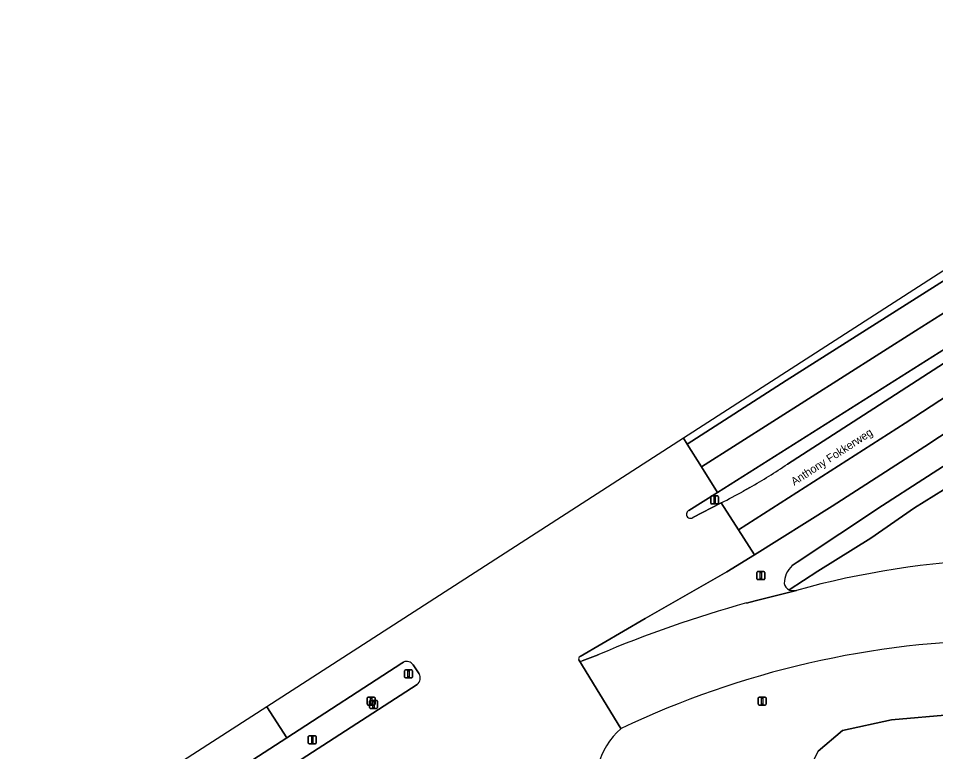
# Model space of a CAD drawing. Extents: x 156061 to 157804, y 383437 to 385640.
# Drawn here: x 156312.5 to 156427.2, y 385531.8 to 385623.4 of the extents above; entities that cross this region are included whole.
import ezdxf

# ---------------------------------------------------------------- set-up
doc = ezdxf.new("R2010")
doc.units = 0
for name, color, linetype in [('IMGEO_Afsluitpaal', 7, 'Continuous'), ('IMGEO_Berm_groen', 7, 'Continuous'), ('IMGEO_Groenvoorziening', 7, 'Continuous'), ('IMGEO_Lichtmast', 7, 'Continuous'), ('IMGEO_Openbare_ruimte_label', 7, 'Continuous'), ('IMGEO_Rijbaan_regionaal_gesloten', 7, 'Continuous'), ('IMGEO_Verkeersregelinstallatiepaal', 7, 'Continuous')]:
    doc.layers.add(name, color=color, linetype=linetype)

msp = doc.modelspace()

# ---------------------------------------------------------------- linework, layer by layer
at = {"layer": 'IMGEO_Afsluitpaal'}
for p, q in [((156360.89, 385542.03), (156361.68, 385542.03)), ((156361.68, 385542.03), (156360.89, 385542.03)), ((156360.79, 385541.13), (156360.79, 385541.93)), ((156360.79, 385541.93), (156360.79, 385541.13)), ((156361.68, 385541.03), (156360.89, 385541.03)), ((156360.89, 385541.03), (156361.68, 385541.03)), ((156361.78, 385541.93), (156361.78, 385541.13)), ((156361.78, 385541.13), (156361.78, 385541.93))]:
    msp.add_line(p, q, dxfattribs=at)
msp.add_lwpolyline([(156361.21, 385541.91), (156361.36, 385541.91), (156361.36, 385541.16), (156361.21, 385541.16), (156361.21, 385541.91)], dxfattribs=at)
for centre, start, end in [((156360.89, 385541.93), 90, 180), ((156360.89, 385541.93), 90, 180), ((156361.68, 385541.93), 0, 90), ((156361.68, 385541.93), 360, 90), ((156360.89, 385541.13), 180, 270), ((156360.89, 385541.13), 180, 270), ((156361.68, 385541.13), 270, 0), ((156361.68, 385541.13), 270, 0)]:
    msp.add_arc(centre, 0.1, start, end, dxfattribs=at)
at = {"layer": 'IMGEO_Berm_groen'}
for points in [[(156457.74, 385603.2), (156468.38, 385609.76), (156480.27, 385617.44), (156479.29, 385619.28), (156457.09, 385604.88), (156455.56, 385603.39), (156444.2, 385592.17), (156399.89, 385564.2), (156396.33, 385561.96)], [(156444.61, 385578.21), (156455.02, 385584.79), (156465.42, 385591.01), (156476.98, 385597.97), (156487.09, 385604.63), (156485.35, 385607.89), (156485.17, 385608.23), (156485.15, 385608.27), (156484.49, 385607.86), (156457.48, 385590.81), (156425.8, 385569.95), (156414.23, 385562.48), (156404.5, 385556.42), (156401.07, 385554.28), (156390.85, 385548.47), (156382.74, 385543.7)], [(156408.65, 385567.73), (156419.41, 385574.67), (156445.92, 385591.78), (156451.49, 385597.23), (156457.74, 385603.2)], [(156448.31, 385577.75), (156469.59, 385590.66), (156475.53, 385594.14), (156477.95, 385595.67), (156479.09, 385596.28), (156479.97, 385596.92), (156480.06, 385597.32), (156479.81, 385597.66), (156479.16, 385598.78), (156477.29, 385597.6), (156477.23, 385597.74), (156477.09, 385597.89), (156476.98, 385597.97), (156465.42, 385591.01), (156455.02, 385584.79), (156444.61, 385578.21), (156435.65, 385572.32), (156420.52, 385562.55), (156409.83, 385555.49), (156409.23, 385555.06)], [(156408.84, 385552.01), (156412.43, 385554.36), (156419.05, 385558.49), (156424.52, 385562.26), (156435.37, 385569.02), (156448.31, 385577.75)], [(156409.23, 385555.06), (156409.83, 385555.49), (156420.52, 385562.55), (156435.65, 385572.32), (156444.61, 385578.21)], [(156403.12, 385564.35), (156403.94, 385564.81)], [(156396.81, 385561.05), (156400.34, 385562.89)], [(156403.53, 385550.38), (156404.62, 385550.66), (156408.45, 385551.63), (156409.77, 385551.96)], [(156382.96, 385543.18), (156384.96, 385543.9)], [(156360.66, 385543), (156360.46, 385542.87), (156346.09, 385533.56), (156314.1, 385512.84), (156302.47, 385505.41), (156290.49, 385497.87), (156278.52, 385490.5), (156266.95, 385483.55), (156254.78, 385476.36), (156243.16, 385469.51), (156215.23, 385452.76), (156213.93, 385451.91), (156195.47, 385439.96), (156146.25, 385408.11), (156122.36, 385392.42), (156089.02, 385370.47), (156093.27, 385365.39), (156145.76, 385399.91), (156224.68, 385450.98), (156281.69, 385487.99)], [(156362.63, 385541.55), (156361.86, 385542.66)], [(156281.69, 385487.99), (156347.87, 385530.83), (156362.36, 385540.21)]]:
    msp.add_lwpolyline(points, dxfattribs=at)
for centre, radius, start, end in [((156366.85, 385629.96), 74.96, 299.6531, 303.8885), ((156367.11, 385629.37), 74.32, 296.5575, 298.9833), ((156396.53, 385561.48), 0.514, 112.6751, 303.3116), ((156411.21, 385552.84), 2.97, 131.8011, 180.4497), ((156411.21, 385552.84), 2.97, 131.8011, 180.4497), ((156409.35, 385553.02), 1.13, 190.1722, 243.0679), ((156409.35, 385553.02), 1.13, 190.1722, 243.0679), ((156409.41, 385554.2), 2.27, 255.3537, 279.1177), ((156442.04, 385410.19), 145.39, 105.3614, 113.1203), ((156382.81, 385543.42), 0.286, 104.0075, 212.3897), ((156382.81, 385543.42), 0.286, 212.5197, 303.0942), ((156361.07, 385542.15), 0.941, 32.4846, 115.7756), ((156361.67, 385541.05), 1.08, 309.1218, 27.5505)]:
    msp.add_arc(centre, radius, start, end, dxfattribs=at)
at = {"layer": 'IMGEO_Groenvoorziening'}
for points in [[(156468.78, 385577.15), (156480.52, 385584.84), (156488.02, 385589.35), (156488.76, 385590.11), (156490.06, 385591.44), (156490.74, 385593.18), (156490.76, 385594.73), (156490.37, 385597.17), (156489.79, 385599.31), (156488.68, 385601.91), (156488.03, 385602.99), (156479.81, 385597.66), (156480.06, 385597.32), (156479.97, 385596.92), (156479.09, 385596.28), (156477.95, 385595.67), (156475.53, 385594.14), (156469.59, 385590.66), (156448.31, 385577.75), (156435.37, 385569.02), (156424.52, 385562.26), (156419.05, 385558.49), (156412.43, 385554.36), (156408.84, 385552.01)], [(156421.05, 385521.05), (156420.41, 385521.52), (156415.25, 385524.03), (156410.61, 385528.11), (156412.46, 385531.88), (156415.53, 385534.45), (156421.65, 385535.79), (156429.28, 385536.44), (156437.02, 385537.14), (156443.94, 385536.91), (156448.64, 385536.45)], [(156448.64, 385536.45), (156443.94, 385536.91), (156437.02, 385537.14), (156429.28, 385536.44), (156421.65, 385535.79), (156415.53, 385534.45), (156412.46, 385531.88), (156410.61, 385528.11), (156415.25, 385524.03), (156420.41, 385521.52), (156421.05, 385521.05)]]:
    msp.add_lwpolyline(points, dxfattribs=at)
for centre, radius, start, end in [((156439.11, 385445.67), 110.27, 92.3086, 105.432), ((156409.41, 385554.2), 2.27, 255.3537, 279.1177), ((156436.88, 385431.39), 114.37, 90.4701, 115.3908), ((156393.85, 385527.79), 9.17, 130.9564, 200.9024)]:
    msp.add_arc(centre, radius, start, end, dxfattribs=at)
at = {"layer": 'IMGEO_Lichtmast'}
for p, q in [((156404.81, 385553.41), (156404.81, 385554.21)), ((156404.81, 385554.21), (156404.81, 385553.41)), ((156404.91, 385554.31), (156405.7, 385554.31)), ((156405.7, 385554.31), (156404.91, 385554.31)), ((156405.8, 385554.21), (156405.8, 385553.41)), ((156405.8, 385553.41), (156405.8, 385554.21)), ((156405.7, 385553.31), (156404.91, 385553.31)), ((156404.91, 385553.31), (156405.7, 385553.31)), ((156405.08, 385538.63), (156405.87, 385538.63)), ((156405.87, 385538.63), (156405.08, 385538.63)), ((156404.98, 385537.73), (156404.98, 385538.53)), ((156404.98, 385538.53), (156404.98, 385537.73)), ((156405.87, 385537.63), (156405.08, 385537.63)), ((156405.08, 385537.63), (156405.87, 385537.63)), ((156405.97, 385538.53), (156405.97, 385537.73)), ((156405.97, 385537.73), (156405.97, 385538.53))]:
    msp.add_line(p, q, dxfattribs=at)
for points in [[(156405.23, 385554.18), (156405.38, 385554.18), (156405.38, 385553.43), (156405.23, 385553.43), (156405.23, 385554.18)], [(156405.4, 385538.51), (156405.55, 385538.51), (156405.55, 385537.76), (156405.4, 385537.76), (156405.4, 385538.51)]]:
    msp.add_lwpolyline(points, dxfattribs=at)
for centre, start, end in [((156404.91, 385554.21), 90, 180), ((156404.91, 385554.21), 90, 180), ((156405.7, 385554.21), 0, 90), ((156405.7, 385554.21), 360, 90), ((156404.91, 385553.41), 180, 270), ((156404.91, 385553.41), 180, 270), ((156405.7, 385553.41), 270, 0), ((156405.7, 385553.41), 270, 0), ((156405.08, 385538.53), 90, 180), ((156405.08, 385538.53), 90, 180), ((156405.87, 385538.53), 0, 90), ((156405.87, 385538.53), 360, 90), ((156405.08, 385537.73), 180, 270), ((156405.08, 385537.73), 180, 270), ((156405.87, 385537.73), 270, 0), ((156405.87, 385537.73), 270, 0)]:
    msp.add_arc(centre, 0.1, start, end, dxfattribs=at)
at = {"layer": 'IMGEO_Rijbaan_regionaal_gesloten'}
for points in [[(156395.65, 385570.97), (156396.11, 385570.23), (156408.46, 385578.16), (156443.47, 385600.32), (156460.47, 385611.21), (156477.84, 385622.02), (156477.19, 385623.23), (156477.09, 385623.42)], [(156457.09, 385604.88), (156479.29, 385619.28), (156478.07, 385621.57), (156477.84, 385622.02), (156460.47, 385611.21), (156443.47, 385600.32), (156408.46, 385578.16), (156396.11, 385570.23), (156397.88, 385567.41), (156424.62, 385584.37)], [(156457.48, 385590.81), (156484.49, 385607.86), (156485.15, 385608.27), (156483.26, 385611.82), (156471.7, 385604.33), (156458, 385595.49), (156423.35, 385572.86), (156402.5, 385559.52), (156404.5, 385556.42), (156414.23, 385562.48), (156425.8, 385569.95)], [(156444.2, 385592.17), (156455.56, 385603.39), (156457.09, 385604.88), (156424.62, 385584.37), (156397.88, 385567.41), (156399.89, 385564.2)]]:
    msp.add_lwpolyline(points, close=True, dxfattribs=at)
for points in [[(156458, 385595.49), (156471.7, 385604.33), (156483.26, 385611.82), (156481.73, 385614.7), (156445.92, 385591.78), (156419.41, 385574.67), (156408.65, 385567.73)], [(156400.34, 385562.89), (156402.5, 385559.52), (156423.35, 385572.86), (156458, 385595.49)], [(156396.33, 385561.96), (156399.89, 385564.2), (156397.88, 385567.41), (156396.11, 385570.23), (156395.65, 385570.97), (156343.56, 385537.43)], [(156403.94, 385564.81), (156403.12, 385564.35)], [(156382.74, 385543.7), (156390.85, 385548.47), (156401.07, 385554.28), (156404.5, 385556.42), (156402.5, 385559.52), (156400.34, 385562.89), (156396.81, 385561.05)], [(156409.77, 385551.96), (156408.45, 385551.63), (156404.62, 385550.66), (156403.53, 385550.38)], [(156382.57, 385543.27), (156387.83, 385534.72)], [(156387.83, 385534.72), (156382.57, 385543.27)], [(156384.96, 385543.9), (156382.96, 385543.18)], [(156343.56, 385537.43), (156346.09, 385533.56), (156360.46, 385542.87), (156360.66, 385543)], [(156361.86, 385542.66), (156362.63, 385541.55)], [(156362.36, 385540.21), (156347.87, 385530.83), (156357.59, 385515.73), (156362.88, 385518.97)], [(156083.92, 385370.25), (156085.61, 385368.22), (156089.02, 385370.47), (156122.36, 385392.42), (156146.25, 385408.11), (156195.47, 385439.96), (156213.93, 385451.91), (156215.23, 385452.76), (156243.16, 385469.51), (156254.78, 385476.36), (156266.95, 385483.55), (156278.52, 385490.5), (156290.49, 385497.87), (156302.47, 385505.41), (156314.1, 385512.84), (156346.09, 385533.56), (156343.56, 385537.43), (156083.92, 385370.25)]]:
    msp.add_lwpolyline(points, dxfattribs=at)
for centre, radius, start, end in [((156366.85, 385629.96), 74.96, 299.6531, 303.8885), ((156367.11, 385629.37), 74.32, 296.5575, 298.9833), ((156396.53, 385561.48), 0.514, 112.6751, 303.3116), ((156439.11, 385445.67), 110.27, 92.3086, 105.432), ((156442.04, 385410.19), 145.39, 105.3614, 113.1203), ((156436.88, 385431.39), 114.37, 90.4701, 115.3908), ((156382.81, 385543.42), 0.286, 104.0075, 212.3897), ((156382.81, 385543.42), 0.286, 212.5197, 303.0942), ((156361.07, 385542.15), 0.941, 32.4846, 115.7756), ((156361.67, 385541.05), 1.08, 309.1218, 27.5505), ((156393.85, 385527.79), 9.17, 130.9564, 200.9024)]:
    msp.add_arc(centre, radius, start, end, dxfattribs=at)
at = {"layer": 'IMGEO_Verkeersregelinstallatiepaal'}
for p, q in [((156399.04, 385562.86), (156399.04, 385563.66)), ((156399.04, 385563.66), (156399.04, 385562.86)), ((156399.14, 385563.76), (156399.92, 385563.76)), ((156399.92, 385563.76), (156399.14, 385563.76)), ((156399.92, 385562.76), (156399.14, 385562.76)), ((156399.14, 385562.76), (156399.92, 385562.76)), ((156400.02, 385563.66), (156400.02, 385562.86)), ((156400.02, 385562.86), (156400.02, 385563.66)), ((156356.21, 385538.63), (156357, 385538.63)), ((156357, 385538.63), (156356.21, 385538.63)), ((156356.11, 385537.73), (156356.11, 385538.53)), ((156356.11, 385538.53), (156356.11, 385537.73)), ((156357, 385537.63), (156356.21, 385537.63)), ((156356.21, 385537.63), (156357, 385537.63)), ((156356.4, 385537.32), (156356.4, 385538.12)), ((156356.4, 385538.12), (156356.4, 385537.32)), ((156356.5, 385538.22), (156357.29, 385538.22)), ((156357.29, 385538.22), (156356.5, 385538.22)), ((156357.1, 385538.53), (156357.1, 385537.73)), ((156357.1, 385537.73), (156357.1, 385538.53)), ((156357.39, 385538.12), (156357.39, 385537.32)), ((156357.39, 385537.32), (156357.39, 385538.12)), ((156357.29, 385537.22), (156356.5, 385537.22)), ((156356.5, 385537.22), (156357.29, 385537.22)), ((156348.76, 385532.89), (156348.76, 385533.69)), ((156348.76, 385533.69), (156348.76, 385532.89)), ((156348.86, 385533.79), (156349.65, 385533.79)), ((156349.65, 385533.79), (156348.86, 385533.79)), ((156349.75, 385533.69), (156349.75, 385532.89)), ((156349.75, 385532.89), (156349.75, 385533.69)), ((156349.65, 385532.79), (156348.86, 385532.79)), ((156348.86, 385532.79), (156349.65, 385532.79))]:
    msp.add_line(p, q, dxfattribs=at)
for points in [[(156399.46, 385563.63), (156399.61, 385563.63), (156399.61, 385562.88), (156399.46, 385562.88), (156399.46, 385563.63)], [(156356.53, 385538.51), (156356.68, 385538.51), (156356.68, 385537.76), (156356.53, 385537.76), (156356.53, 385538.51)], [(156356.82, 385538.09), (156356.97, 385538.09), (156356.97, 385537.34), (156356.82, 385537.34), (156356.82, 385538.09)], [(156349.18, 385533.67), (156349.33, 385533.67), (156349.33, 385532.92), (156349.18, 385532.92), (156349.18, 385533.67)]]:
    msp.add_lwpolyline(points, dxfattribs=at)
for centre, start, end in [((156399.14, 385563.66), 90, 180), ((156399.14, 385563.66), 90, 180), ((156399.14, 385562.86), 180, 270), ((156399.14, 385562.86), 180, 270), ((156399.92, 385563.66), 0, 90), ((156399.92, 385563.66), 360, 90), ((156399.92, 385562.86), 270, 0), ((156399.92, 385562.86), 270, 0), ((156356.21, 385538.53), 90, 180), ((156356.21, 385538.53), 90, 180), ((156357, 385538.53), 0, 90), ((156357, 385538.53), 360, 90), ((156356.21, 385537.73), 180, 270), ((156356.21, 385537.73), 180, 270), ((156356.5, 385538.12), 90, 180), ((156356.5, 385538.12), 90, 180), ((156357, 385537.73), 270, 0), ((156357, 385537.73), 270, 0), ((156357.29, 385538.12), 0, 90), ((156357.29, 385538.12), 360, 90), ((156356.5, 385537.32), 180, 270), ((156356.5, 385537.32), 180, 270), ((156357.29, 385537.32), 270, 0), ((156357.29, 385537.32), 270, 0), ((156348.86, 385533.69), 90, 180), ((156348.86, 385533.69), 90, 180), ((156348.86, 385532.89), 180, 270), ((156348.86, 385532.89), 180, 270), ((156349.65, 385533.69), 0, 90), ((156349.65, 385533.69), 360, 90), ((156349.65, 385532.89), 270, 0), ((156349.65, 385532.89), 270, 0)]:
    msp.add_arc(centre, 0.1, start, end, dxfattribs=at)

# ---------------------------------------------------------------- texts
at = {"layer": 'IMGEO_Openbare_ruimte_label'}
msp.add_text('Anthony Fokkerweg', height=1, rotation=32.959, dxfattribs=at).set_placement((156409.48, 385565.02))

doc.saveas('drawing.dxf')
